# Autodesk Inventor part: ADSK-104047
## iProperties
Shininess: 0.0
Created: 2000-11
Part Number: ADSK-104047
Description: AISI 1040 DIA. 2-1/4" x 20" LONG
Document SubType Name: Modeling
Stock Number: ADSK-104047
Density: 1 g/cm^3
Density: 0.0
Volumn: 0.0
Area: 0.0
PropertySet Name: Model Information
Control State: 0
Master: False
Checked Out: False
Author: gao
